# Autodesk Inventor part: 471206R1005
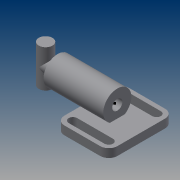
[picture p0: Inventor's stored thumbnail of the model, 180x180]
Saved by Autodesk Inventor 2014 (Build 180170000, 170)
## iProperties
Created: 2017-12
Part Number: 471206R1005
Material: 일반
Document SubType Name: Modeling
Designer: MJ-PARK
Density: 1 g/cm^3
Appearance: 기본값
Author: MJ-PARK
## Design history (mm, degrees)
sketch "스케치1"
  geometry: L1 (21, 38)-(-21, 38); L2 (-31, 28)-(-31, -28); L3 (-21, -38)-(21, -38); L4 (31, -28)-(31, 28); L5 (31, 38)-(-31, -38); L6 (-31, 38)-(31, -38); L7 (-21, 28)-(21, 28); L8 (-21, 23)-(21, 23); L9 (21, 33)-(-21, 33); L10 (-21, -28)-(21, -28); L11 (-21, -33)-(21, -33); L12 (21, -23)-(-21, -23); A1 r 10 centre (-21, 28) between (-21, 38) and (-31, 28); A2 r 10 centre (21, 28) between (31, 28) and (21, 38); A3 r 10 centre (-21, -28) between (-31, -28) and (-21, -38); A4 r 10 centre (21, -28) between (21, -38) and (31, -28); A5 r 5 centre (-21, 28) between (-21, 33) and (-21, 23); A6 r 5 centre (21, 28) between (21, 23) and (21, 33); A7 r 5 centre (-21, -28) between (-21, -23) and (-21, -33); A8 r 5 centre (21, -28) between (21, -33) and (21, -23); 3 further points
  constraints: 28 end point, 16 point on circle, 16 tangent, 8 centre point, 8 point on line, 6 parallel, 4 midpoint, 3 equal radius, 1 horizontal, 1 perpendicular
  dimensions: "d0" = 76 distance of L6.end L5.start; "d1" = 62 distance of L5.end L6.end; "d2" = 10 radius of A1; "d3" = 10 diameter of A6; "d4" = 10 diameter of A8
extrude "돌출1" new body sketch "스케치1" distance "d5" = 10; taper "d6" = 0 deg
node "작업 평면1"
sketch "스케치2"
  geometry: L1 (28, 0)-(28, 24); C1 r 6 at (28, 24); C2 r 16.5 at (28, 24)
  constraints: 2 centre point, 2 coincident, 2 end point, 1 vertical
  dimensions: "d8" = 24 distance of L1.start L1.end; "d9" = 12 diameter of C1; "d10" = 33 diameter of C2
extrude "돌출2" join sketch "스케치2" distance "d11" = 70; taper "d12" = 0 deg
sketch "스케치3"
  geometry: C1 r 6 at (-28, 24); A1 r 16.5 centre (-28, 24) between (-19.268, 10) and (-36.732, 10) reference; 1 further point
  constraints: 1 centre point, 1 coincident
  dimensions: "d13" = 12 diameter of C1
extrude "돌출3" cut sketch "스케치3" distance "d14" = 12; taper "d15" = 0 deg
node "작업 평면2"
sketch "스케치5"
  geometry: L1 (-31, 8.732)-(3, 8.732) reference; L2 (-31, -8.732)-(-31, 8.732) reference; L3 (3, -8.732)-(-31, -8.732) reference; L4 (3, 8.732)-(3, -8.732) reference; L5 (-67, 16.5)-(-67, -16.5) reference; L6 (-67, 0)-(-81, 0); C1 r 8 at (-81, 0); 1 further point
  constraints: 2 end point, 1 centre point, 1 coincident, 1 midpoint, 1 perpendicular
  dimensions: "d17" = 14 distance of L6.start L6.end; "d18" = 16 diameter of C1
extrude "돌출4" join sketch "스케치5" stored distance "d19" = 44; taper "d20" = 0 deg
sketch "스케치6"
  geometry: 1 further point
sketch "스케치7"
  geometry: C1 r 16.5 at (0, 0) reference; C2 r 8 at (0, 0); 1 further point
  constraints: 1 centre point, 1 coincident
  dimensions: "d21" = 16 diameter of C2
extrude "돌출5" join sketch "스케치7" stored distance "d22" = 44; taper "d23" = 0 deg
node "솔리드1"
node "투영된 루프1"
other parameters: "d7" = -34, "d16" = 24
